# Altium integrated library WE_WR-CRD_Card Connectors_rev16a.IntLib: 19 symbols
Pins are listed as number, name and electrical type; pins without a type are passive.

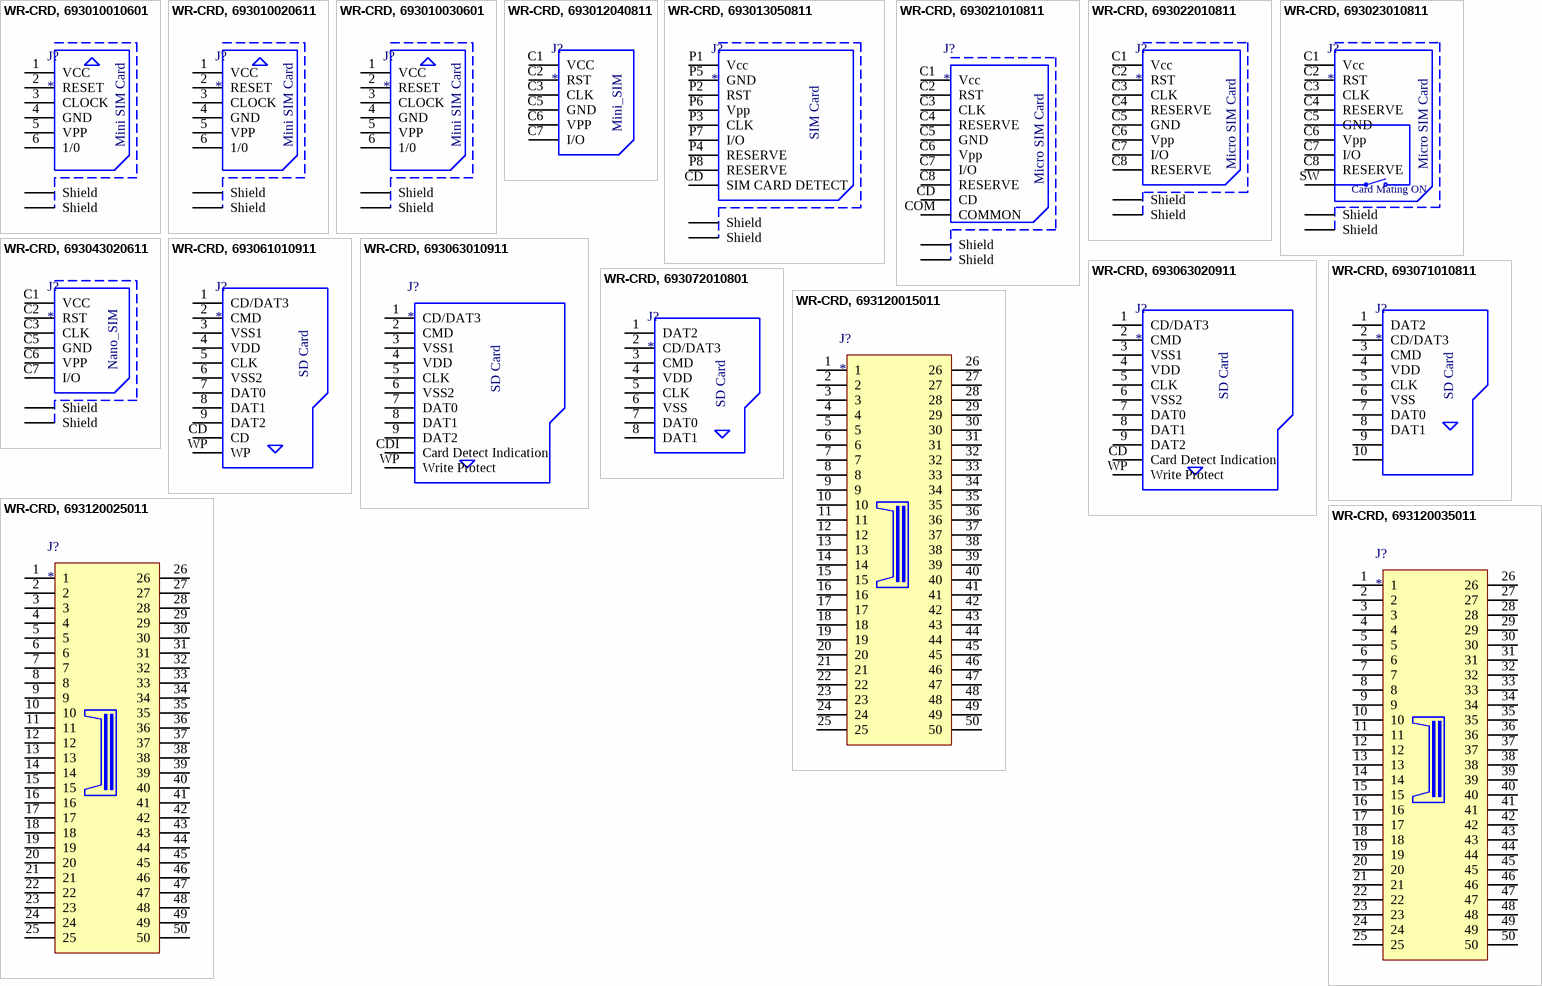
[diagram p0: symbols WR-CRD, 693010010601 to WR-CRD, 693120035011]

## WR-CRD, 693010010601
designator J?
WR-CRD Mini SIM_Standard Header; Manufacturer: Würth Elektronik eiSos GmbH; partNo: 693010010601; ComponentLink1 Description: Manufacturer; ComponentLink2 Description: Datasheet; NoPins: 6
footprint 693010010601
pins: 1 VCC, 2 RESET, 3 CLOCK, 4 GND, 5 VPP, 6 1/0, Z1 Shield, Z2 Shield

## WR-CRD, 693010020611
designator J?
WR-CRD Mini SIM; Manufacturer: Würth Elektronik eiSos GmbH; partNo: 693010020611; ComponentLink1 Description: Manufacturer; ComponentLink2 Description: Datasheet; NoPins: 6
footprint 693010020611
pins: 1 VCC, 2 RESET, 3 CLOCK, 4 GND, 5 VPP, 6 1/0, Z1 Shield, Z2 Shield

## WR-CRD, 693010030601
designator J?
WR-CRD Mini SIM; Manufacturer: Würth Elektronik eiSos GmbH; partNo: 693010030601; ComponentLink1 Description: Manufacturer; ComponentLink2 Description: Datasheet; NoPins: 6
footprint 693010030601
pins: 1 VCC, 2 RESET, 3 CLOCK, 4 GND, 5 VPP, 6 1/0, Z1 Shield, Z2 Shield

## WR-CRD, 693012040811
designator J?
WR-CRD mini SIM_Hinge type_6 pins; Manufacturer: Würth Elektronik eiSos GmbH; partNo: 693012040811; ComponentLink1 Description: Manufacturer; ComponentLink2 Description: Datasheet; NoPins: 6
footprint 693012040811
pins: C1 VCC, C2 RST, C3 CLK, C5 GND, C6 VPP, C7 I/O

## WR-CRD, 693013050811
designator J?
WR-CRD Mega SIM_Push and Push_8 pins; Manufacturer: Würth Elektronik eiSos GmbH; partNo: 693013050811; ComponentLink1 Description: Manufacturer; ComponentLink2 Description: Datasheet; NoPins: 9
footprint 693013050811
pins: CD SIM CARD DETECT, P1 Vcc, P2 RST, P3 CLK, P4 RESERVE, P5 GND, P6 Vpp, P7 I/O, P8 RESERVE, Z1 Shield, Z2 Shield

## WR-CRD, 693021010811
designator J?
WR-CRD Micro SIM_Push and Push_8 pins; Manufacturer: Würth Elektronik eiSos GmbH; partNo: 693021010811; ComponentLink1 Description: Manufacturer; ComponentLink2 Description: Datasheet; NoPins: 10
footprint 693021010811
pins: C1 Vcc, C2 RST, C3 CLK, C4 RESERVE, C5 GND, C6 Vpp, C7 I/O, C8 RESERVE, CD, COM COMMON, Z1 Shield, Z2 Shield

## WR-CRD, 693022010811
designator J?
WR-CRD Micro SIM_Hinge_8 pins; Manufacturer: Würth Elektronik eiSos GmbH; partNo: 693022010811; ComponentLink1 Description: Manufacturer; ComponentLink2 Description: Datasheet; NoPins: 8
footprint 693022010811
pins: C1 Vcc, C2 RST, C3 CLK, C4 RESERVE, C5 GND, C6 Vpp, C7 I/O, C8 RESERVE, Z1 Shield, Z2 Shield

## WR-CRD, 693023010811
designator J?
WR-CRD Micro SIM_Push and Pull_8 pins; Manufacturer: Würth Elektronik eiSos GmbH; partNo: 693023010811; ComponentLink1 Description: Manufacturer; ComponentLink2 Description: Datasheet; NoPins: 9
footprint 693023010811
pins: C1 Vcc, C2 RST, C3 CLK, C4 RESERVE, C5 GND, C6 Vpp, C7 I/O, C8 RESERVE, SW, Z1 Shield, Z2 Shield

## WR-CRD, 693043020611
designator J?
WR-CRD Nano SIM_Push and Pull_6 pins; Manufacturer: Würth Elektronik eiSos GmbH; partNo: 693043020611; ComponentLink1 Description: Manufacturer; ComponentLink2 Description: Datasheet; NoPins: 6
footprint 693043020611
pins: C1 VCC, C2 RST, C3 CLK, C5 GND, C6 VPP, C7 I/O, Z1 Shield, Z2 Shield

## WR-CRD, 693061010911
designator J?
WR-CRD SD_Push and Push; Manufacturer: Würth Elektronik eiSos GmbH; partNo: 693061010911; ComponentLink1 Description: Manufacturer; ComponentLink2 Description: Datasheet; NoPins: 11
footprint 693061010911 (WR-CRD SD_Push and Push_with card detection_9 pins)
pins: 1 CD/DAT3, 2 CMD, 3 VSS1, 4 VDD, 5 CLK, 6 VSS2, 7 DAT0, 8 DAT1, 9 DAT2, CD, WP

## WR-CRD, 693063010911
designator J?
WR-CRD SD_Push and Pull; Manufacturer: Würth Elektronik eiSos GmbH; partNo: 693063010911; ComponentLink1 Description: Manufacturer; ComponentLink2 Description: Datasheet; NoPins: 11
footprint 693063010911
pins: 1 CD/DAT3, 2 CMD, 3 VSS1, 4 VDD, 5 CLK, 6 VSS2, 7 DAT0, 8 DAT1, 9 DAT2, CDI Card Detect Indication, WP Write Protect

## WR-CRD, 693063020911
designator J?
WR-CRD SD_Push and Pull; Manufacturer: Würth Elektronik eiSos GmbH; partNo: 693063020911; ComponentLink1 Description: Manufacturer; ComponentLink2 Description: Datasheet; NoPins: 11
footprint 693063020911
pins: 1 CD/DAT3, 2 CMD, 3 VSS1, 4 VDD, 5 CLK, 6 VSS2, 7 DAT0, 8 DAT1, 9 DAT2, CD Card Detect Indication, WP Write Protect

## WR-CRD, 693071010811
designator J?
WR-CRD Micro SD_Push and Push; Manufacturer: Würth Elektronik eiSos GmbH; partNo: 693071010811; ComponentLink1 Description: Manufacturer; ComponentLink2 Description: Datasheet; NoPins: 8
footprint 693071010811
pins: 1 DAT2, 2 CD/DAT3, 3 CMD, 4 VDD, 5 CLK, 6 VSS, 7 DAT0, 8 DAT1, 9, 10

## WR-CRD, 693072010801
designator J?
WR-CRD Micro SD_Hinge; Manufacturer: Würth Elektronik eiSos GmbH; partNo: 693072010801; ComponentLink1 Description: Manufacturer; ComponentLink2 Description: Datasheet; NoPins: 8
footprint 693072010801
pins: 1 DAT2, 2 CD/DAT3, 3 CMD, 4 VDD, 5 CLK, 6 VSS, 7 DAT0, 8 DAT1

## WR-CRD, 693120015011
designator J?
WR-Compact Flash_Header; Manufacturer: Würth Elektronik eiSos GmbH; partNo: 693120015011; ComponentLink1 Description: Manufacturer; ComponentLink2 Description: Datasheet; NoPins: 50
footprint 693120015011
pins: 1, 2, 3, 4, 5, 6, 7, 8, 9, 10, 11, 12, 13, 14, 15, 16, 17, 18, 19, 20, 21, 22, 23, 24, 25, 26, 27, 28, 29, 30, 31, 32, 33, 34, 35, 36, 37, 38, 39, 40, 41, 42, 43, 44, 45, 46, 47, 48, 49, 50

## WR-CRD, 693120025011
designator J?
WR-Compact Flash_Reverse Header; Manufacturer: Würth Elektronik eiSos GmbH; partNo: 693120025011; ComponentLink1 Description: Manufacturer; ComponentLink2 Description: Datasheet; NoPins: 50
footprint 693120025011
pins: 1, 2, 3, 4, 5, 6, 7, 8, 9, 10, 11, 12, 13, 14, 15, 16, 17, 18, 19, 20, 21, 22, 23, 24, 25, 26, 27, 28, 29, 30, 31, 32, 33, 34, 35, 36, 37, 38, 39, 40, 41, 42, 43, 44, 45, 46, 47, 48, 49, 50

## WR-CRD, 693120035011
designator J?
WR-Compact Flash_Shrouded; Manufacturer: Würth Elektronik eiSos GmbH; partNo: 693120035011; ComponentLink1 Description: Manufacturer; ComponentLink2 Description: Datasheet; NoPins: 50
footprint 693120035011
pins: 1, 2, 3, 4, 5, 6, 7, 8, 9, 10, 11, 12, 13, 14, 15, 16, 17, 18, 19, 20, 21, 22, 23, 24, 25, 26, 27, 28, 29, 30, 31, 32, 33, 34, 35, 36, 37, 38, 39, 40, 41, 42, 43, 44, 45, 46, 47, 48, 49, 50


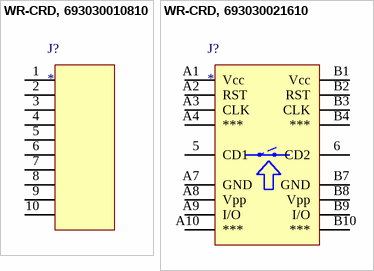
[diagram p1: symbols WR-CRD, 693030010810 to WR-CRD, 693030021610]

## WR-CRD, 693030010810
designator J?
WR-CRD Smart Card_Header type_8 pins; Manufacturer: Würth Elektronik eiSos GmbH; partNo: 693030010810; ComponentLink1 Description: Manufacturer; ComponentLink2 Description: Datasheet; NoPins: 10
footprint 693030010810
pins: 1, 2, 3, 4, 5, 6, 7, 8, 9, 10

## WR-CRD, 693030021610
designator J?
WR-CRD Smart Card_Dual-way Header type_16 pins; Manufacturer: Würth Elektronik eiSos GmbH; partNo: 693030021610; ComponentLink1 Description: Manufacturer; ComponentLink2 Description: Datasheet; NoPins: 18
footprint 693030021610
pins: 5 CD1, 6 CD2, A1 Vcc, A2 RST, A3 CLK, A4 ***, A7 GND, A8 Vpp, A9 I/O, A10 ***, B1 Vcc, B2 RST, B3 CLK, B4 ***, B7 GND, B8 Vpp, B9 I/O, B10 ***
